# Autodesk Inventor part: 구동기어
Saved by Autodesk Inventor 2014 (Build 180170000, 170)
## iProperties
Created: 2026-09
Part Number: 구동기어
Material: 강철, 합금
Document SubType Name: Modeling
Designer: dg
Density: 7.85 g/cm^3
Appearance: 반연마
Mass: 220.892 g
Surface Area: 80.4284 cm^2
Volume: 28.1391 cm^3
Author: jhkim
Creation Date: 2026-08-26
Sending System: Autodesk Inventor 2027
Preprocessor: ST-DEVELOPER v20.1
Author: dg
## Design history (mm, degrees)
node "구동기어1"
node "솔리드1"
node "기준1"
